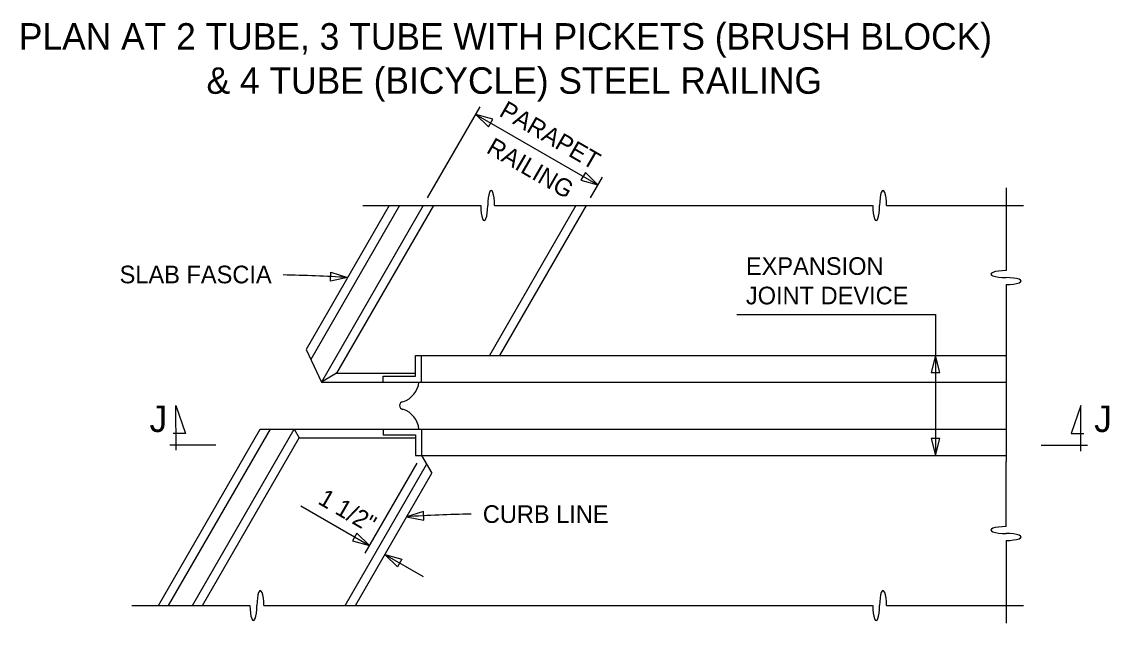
# Model space of a CAD drawing. Extents: x 19590 to 20151, y 19944 to 20103.
# Drawn here: x 19813 to 19841.77, y 20018.34 to 20034.24 of the extents above; entities that cross this region are included whole.
import ezdxf

# ---------------------------------------------------------------- set-up
doc = ezdxf.new("R2010")
doc.units = 0
for name, color, linetype in [('DETAIL_PR', 7, 'Continuous'), ('DETAIL_TEXT_DIMEN_PR', 7, 'Continuous'), ('Level 1', 7, 'Continuous')]:
    doc.layers.add(name, color=color, linetype=linetype)

msp = doc.modelspace()

# ---------------------------------------------------------------- linework, layer by layer
at = {"layer": 'DETAIL_PR'}
for p, q in [((19839.039, 20029.848), (19839.039, 20027.66)), ((19822.725, 20029.382), (19820.525, 20025.572)), ((19822.994, 20029.382), (19820.647, 20025.315)), ((19823.623, 20029.382), (19820.929, 20024.716)), ((19823.892, 20029.382), (19821.333, 20024.95)), ((19822.025, 20029.382), (19825.145, 20029.382)), ((19827.663, 20029.382), (19825.374, 20025.416)), ((19825.512, 20029.382), (19835.512, 20029.382)), ((19827.932, 20029.382), (19825.643, 20025.416)), ((19835.879, 20029.382), (19839.506, 20029.382)), ((19839.039, 20027.293), (19839.039, 20022.617)), ((19820.525, 20025.572), (19820.929, 20024.716)), ((19823.423, 20025.416), (19839.039, 20025.416)), ((19823.423, 20024.872), (19823.423, 20025.416)), ((19823.578, 20024.716), (19823.578, 20025.416)), ((19821.333, 20024.95), (19820.929, 20024.716)), ((19821.333, 20024.95), (19823.423, 20024.95)), ((19820.929, 20024.716), (19822.478, 20024.716)), ((19822.478, 20024.716), (19839.039, 20024.716)), ((19822.567, 20024.872), (19823.423, 20024.872)), ((19822.568, 20024.716), (19822.568, 20024.872)), ((19816.62, 20018.807), (19819.314, 20023.472)), ((19816.889, 20018.807), (19819.583, 20023.472)), ((19817.518, 20018.807), (19820.211, 20023.472)), ((19817.787, 20018.807), (19820.346, 20023.239)), ((19819.314, 20023.472), (19822.568, 20023.472)), ((19820.211, 20023.472), (19820.346, 20023.239)), ((19820.346, 20023.239), (19823.423, 20023.239)), ((19822.567, 20023.317), (19823.423, 20023.317)), ((19822.568, 20023.472), (19822.568, 20023.317)), ((19822.568, 20023.472), (19839.039, 20023.472)), ((19823.423, 20023.317), (19823.423, 20022.772)), ((19823.578, 20023.472), (19823.578, 20022.772)), ((19823.423, 20022.772), (19839.039, 20022.772)), ((19823.578, 20022.772), (19823.848, 20022.306)), ((19821.558, 20018.807), (19823.713, 20022.539)), ((19822.089, 20020.192), (19823.462, 20022.57)), ((19839.039, 20020.896), (19839.039, 20022.617)), ((19821.828, 20018.807), (19823.848, 20022.306)), ((19839.039, 20020.529), (19839.039, 20018.341)), ((19815.92, 20018.807), (19819.04, 20018.807)), ((19819.407, 20018.807), (19835.512, 20018.807)), ((19835.879, 20018.807), (19839.506, 20018.807))]:
    msp.add_line(p, q, dxfattribs=at)
for centre, radius, start, end in [((19822.896, 20024.782), 0.618, 288.1365, 353.9316), ((19823.096, 20024.094), 0.101, 94.4387, 265.5613), ((19822.896, 20023.407), 0.618, 6.0684, 71.8635)]:
    msp.add_arc(centre, radius, start, end, dxfattribs=at)
for centre, major_axis, ratio, start_param, end_param in [((19825.42, 20029.382), (0, -0.398), 0.230204, 1.570796, 4.712389), ((19835.787, 20029.382), (0, -0.398), 0.230204, 1.570796, 4.712389), ((19825.237, 20029.382), (0, -0.398), 0.230206, 4.712389, 7.853982), ((19835.604, 20029.382), (0, -0.398), 0.230206, 4.712389, 7.853982), ((19839.039, 20027.568), (0.398, 0), 0.230204, 1.570796, 4.712389), ((19839.039, 20027.385), (0.398, 0), 0.230206, 4.712389, 7.853982), ((19839.039, 20020.804), (0.398, 0), 0.230204, 1.570796, 4.712389), ((19839.039, 20020.62), (0.398, 0), 0.230206, 4.712389, 7.853982), ((19819.316, 20018.807), (0, -0.398), 0.230204, 1.570796, 4.712389), ((19835.787, 20018.807), (0, -0.398), 0.230204, 1.570796, 4.712389), ((19819.132, 20018.807), (0, -0.398), 0.230206, 4.712389, 7.853982), ((19835.604, 20018.807), (0, -0.398), 0.230206, 4.712389, 7.853982)]:
    msp.add_ellipse(centre, major_axis=major_axis, ratio=ratio, start_param=start_param, end_param=end_param, dxfattribs=at)
at = {"layer": 'DETAIL_TEXT_DIMEN_PR'}
for p, q in [((19823.739, 20029.584), (19825.13, 20031.993)), ((19825.014, 20031.791), (19828.246, 20029.925)), ((19828.049, 20029.584), (19828.363, 20030.127)), ((19831.916, 20026.505), (19837.173, 20026.505)), ((19837.173, 20026.505), (19837.173, 20022.772)), ((19817.085, 20022.913), (19817.084, 20024.094)), ((19817.084, 20024.094), (19817.339, 20023.352)), ((19841.022, 20024.094), (19840.766, 20023.352)), ((19841.021, 20022.886), (19841.022, 20024.094)), ((19817.339, 20023.352), (19817.006, 20023.352)), ((19840.766, 20023.352), (19841.1, 20023.352)), ((19818.134, 20023.045), (19816.917, 20023.045)), ((19839.972, 20023.045), (19841.198, 20023.045)), ((19820.387, 20021.444), (19822.205, 20020.394)), ((19822.609, 20020.161), (19823.619, 20019.578))]:
    msp.add_line(p, q, dxfattribs=at)
for centre, start, end in [((19819.177, 19988.061), 86.4465, 88.9222), ((19825.631, 19981.74), 91.0778, 93.5535)]:
    msp.add_arc(centre, 39.492, start, end, dxfattribs=at)
at = {"layer": 'Level 1'}
for p, q in [((19825.014, 20031.791), (19825.347, 20031.464)), ((19825.464, 20031.666), (19825.014, 20031.791)), ((19825.347, 20031.464), (19825.464, 20031.666)), ((19827.913, 20030.252), (19827.797, 20030.05)), ((19828.246, 20029.925), (19827.913, 20030.252)), ((19827.797, 20030.05), (19828.246, 20029.925)), ((19821.167, 20027.385), (19821.181, 20027.618)), ((19821.181, 20027.618), (19821.625, 20027.477)), ((19821.625, 20027.477), (19821.167, 20027.385)), ((19837.173, 20025.416), (19837.056, 20024.965)), ((19837.29, 20024.965), (19837.173, 20025.416)), ((19837.056, 20024.965), (19837.29, 20024.965)), ((19837.289, 20023.224), (19837.056, 20023.224)), ((19837.056, 20023.224), (19837.173, 20022.772)), ((19837.173, 20022.772), (19837.289, 20023.224)), ((19823.628, 20021.297), (19823.184, 20021.156)), ((19823.641, 20021.064), (19823.628, 20021.297)), ((19823.184, 20021.156), (19823.641, 20021.064)), ((19821.872, 20020.721), (19821.756, 20020.519)), ((19822.205, 20020.394), (19821.872, 20020.721)), ((19821.756, 20020.519), (19822.205, 20020.394)), ((19822.609, 20020.161), (19823.059, 20020.036)), ((19822.942, 20019.834), (19822.609, 20020.161)), ((19823.059, 20020.036), (19822.942, 20019.834))]:
    msp.add_line(p, q, dxfattribs=at)

# ---------------------------------------------------------------- texts
at = {"layer": 'DETAIL_TEXT_DIMEN_PR'}
for s, height, p in [('PLAN AT 2 TUBE, 3 TUBE WITH PICKETS (BRUSH BLOCK)', 0.69987, (19812.927, 20033.501)), (' & 4 TUBE (BICYCLE) STEEL RAILING', 0.69987, (19817.631, 20032.334)), ('EXPANSION ', 0.4665, (19832.159, 20027.547)), ('SLAB FASCIA', 0.46652, (19815.593, 20027.325)), ('JOINT DEVICE', 0.46652, (19832.159, 20026.769)), ('J', 0.7, (19816.384, 20023.395)), ('J', 0.7, (19841.371, 20023.394)), ('CURB LINE', 0.4665, (19825.2, 20020.992))]:
    msp.add_text(s, height=height, dxfattribs=at).set_placement(p)
for s, p in [('PARAPET', (19825.604, 20031.765)), ('RAILING', (19825.266, 20030.793)), ('1 1/2"', (19820.81, 20021.515))]:
    msp.add_text(s, height=0.4665, rotation=330, dxfattribs=at).set_placement(p)

doc.saveas('drawing.dxf')
